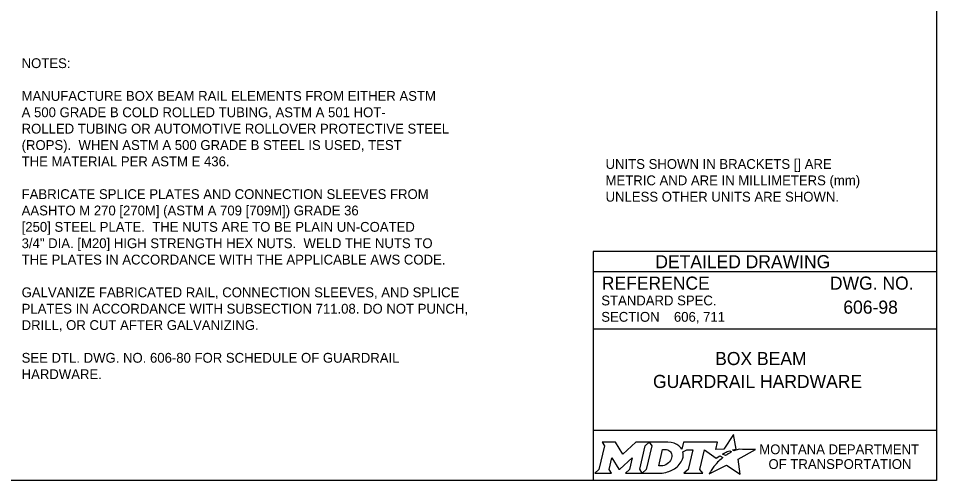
# Model space of a CAD drawing. Extents: x 49991.4 to 50021, y 49987.6 to 50011.4.
# Drawn here: x 50011.14 to 50016.75, y 49987.8 to 49990.62 of the extents above; entities that cross this region are included whole.
import ezdxf

# ---------------------------------------------------------------- set-up
doc = ezdxf.new("R2010")
doc.units = 0
for name, color, linetype in [('Default', 7, 'Continuous'), ('Level 1', 7, 'Continuous'), ('Level 2', 7, 'Continuous'), ('Level 5', 7, 'Continuous')]:
    doc.layers.add(name, color=color, linetype=linetype)

msp = doc.modelspace()

# ---------------------------------------------------------------- linework, layer by layer
at = {"layer": 'Default'}
for points in [[(50015.5126, 49987.9811), (50015.5023, 49987.9867), (50015.5139, 49987.9895), (50015.5255, 49987.9915), (50015.5081, 49988.0816), (50015.4486, 49987.9903), (50015.4013, 49987.9896), (50015.4116, 49988.0337), (50015.2024, 49988.0338), (50015.1923, 49987.9913), (50015.1865, 49987.9996)], [(50014.7056, 49988.0338), (50014.7197, 49988.0104), (50014.6862, 49987.8671), (50014.6605, 49987.8446), (50014.7621, 49987.8446), (50014.7486, 49987.8674), (50014.7648, 49987.9375), (50014.8085, 49987.8685), (50014.8138, 49987.8685), (50014.8889, 49987.938), (50014.8725, 49987.8669), (50014.8478, 49987.8449), (50014.9494, 49987.8449), (50014.9356, 49987.8682), (50014.9688, 49988.0106)], [(50014.9688, 49988.0106), (50014.9941, 49988.0338), (50014.9117, 49988.0338), (50014.8321, 49987.9608), (50014.7876, 49988.0335), (50014.7056, 49988.0338)], [(50015.1077, 49988.0338), (50014.9941, 49988.0338), (50015.0088, 49988.0109), (50014.9749, 49987.8671), (50014.9494, 49987.8449), (50015.06, 49987.8449)], [(50015.1317, 49987.9471), (50015.1305, 49987.939), (50015.1273, 49987.9297), (50015.1231, 49987.9215), (50015.1175, 49987.914), (50015.111, 49987.9071), (50015.1031, 49987.9008), (50015.0948, 49987.8961), (50015.0857, 49987.8922), (50015.0766, 49987.8899), (50015.0674, 49987.889), (50015.0515, 49987.889), (50015.0751, 49987.989), (50015.0911, 49987.989), (50015.0987, 49987.9884), (50015.1063, 49987.9865), (50015.1129, 49987.9835), (50015.119, 49987.9793), (50015.1238, 49987.9743), (50015.1275, 49987.9683), (50015.1302, 49987.9621), (50015.1318, 49987.9547), (50015.1318, 49987.9517), (50015.1317, 49987.9471)], [(50015.1991, 49987.9747), (50015.2237, 49987.9878), (50015.2606, 49987.9878), (50015.232, 49987.8673), (50015.2045, 49987.8446), (50015.3207, 49987.8446), (50015.3037, 49987.8675), (50015.3319, 49987.9877), (50015.4032, 49987.936), (50015.4243, 49987.9511), (50015.444, 49987.9402)], [(50015.3882, 49987.8843), (50015.3729, 49987.8599), (50015.3682, 49987.8524), (50015.3624, 49987.8438), (50015.3601, 49987.8395), (50015.4654, 49987.8926), (50015.5493, 49987.8375), (50015.5362, 49987.9302), (50015.6431, 49987.9886), (50015.5938, 49987.9894), (50015.5637, 49987.9898), (50015.5429, 49987.9901), (50015.5361, 49987.9886), (50015.5312, 49987.9874), (50015.5228, 49987.9851), (50015.5126, 49987.9811)], [(50015.4622, 49987.9535), (50015.4598, 49987.9518), (50015.4415, 49987.9614), (50015.4518, 49987.9671), (50015.4559, 49987.9693), (50015.4645, 49987.9733), (50015.4702, 49987.9759), (50015.4781, 49987.9789), (50015.4854, 49987.9816), (50015.4972, 49987.9742), (50015.4932, 49987.9721), (50015.4886, 49987.9696), (50015.4844, 49987.9674), (50015.4794, 49987.9645), (50015.4775, 49987.9634), (50015.4748, 49987.9618), (50015.4723, 49987.9604), (50015.47, 49987.9588), (50015.4674, 49987.957), (50015.4647, 49987.9552), (50015.4622, 49987.9535)], [(50015.4021, 49987.9004), (50015.4021, 49987.9004)], [(50015.1057, 49987.8522), (50015.1141, 49987.8548), (50015.1271, 49987.8602), (50015.1475, 49987.8712)]]:
    msp.add_lwpolyline(points, dxfattribs=at)
for centre, radius, start, end in [((50015.1308, 49987.9554), 0.0709, 339.5329, 15.8582), ((50015.0868, 49987.9727), 0.1183, 300.9103, 339.1383)]:
    msp.add_arc(centre, radius, start, end, dxfattribs=at)
for centre, major_axis, ratio, start_param, end_param in [((50015.1056, 49987.9864), (0.0834, -0.0037), 0.568097, 0.61298, 1.570796), ((50015.1612, 49987.9937), (0.0361, -0.0295), 0.469099, 1.225588, 1.570796), ((50015.3952, 49987.8923), (-0.00694, -0.00806), 0.008222, 0, 3.137361), ((50015.4119, 49987.9106), (-0.0098, -0.0102), 0.016458, 3.141593, 6.279097), ((50015.4329, 49987.9305), (-0.0112, -0.0097), 0.021651, 3.157348, 6.283185), ((50015.0603, 49987.9932), (0, 0.1484), 0.987302, 3.139398, 3.456847)]:
    msp.add_ellipse(centre, major_axis=major_axis, ratio=ratio, start_param=start_param, end_param=end_param, dxfattribs=at)
at = {"layer": 'Level 1'}
msp.add_lwpolyline([(49999.3835, 49998.9992), (50016.7501, 49998.9992), (50016.7501, 49987.7988), (49999.3835, 49987.7988)], close=True, dxfattribs=at)
at = {"layer": 'Level 5'}
for p, q in [((50016.7501, 49989.1988), (50014.6501, 49989.1988)), ((50014.6501, 49989.1988), (50014.6501, 49987.7988)), ((50016.7501, 49989.0738), (50014.6501, 49989.0738)), ((50016.3862, 49988.8587), (50016.3862, 49988.8587)), ((50015.1444, 49988.7993), (50015.1444, 49988.7993)), ((50016.7501, 49988.7238), (50014.6501, 49988.7238)), ((50015.7001, 49988.4747), (50015.7001, 49988.4747)), ((50016.7501, 49988.1057), (50014.6501, 49988.1057))]:
    msp.add_line(p, q, dxfattribs=at)

# ---------------------------------------------------------------- texts
at = {"layer": 'Default'}
for s, p in [('MONTANA DEPARTMENT', (50015.6663, 49987.96)), ('OF TRANSPORTATION', (50015.7225, 49987.87))]:
    msp.add_text(s, height=0.06, dxfattribs=at).set_placement(p)
at = {"layer": 'Level 2'}
for s, height, p in [('NOTES:', 0.06, (50011.1578, 49990.3191)), ('MANUFACTURE BOX BEAM RAIL ELEMENTS FROM EITHER ASTM', 0.06, (50011.1578, 49990.1191)), ('A 500 GRADE B COLD ROLLED TUBING, ASTM A 501 HOT-', 0.06, (50011.1578, 49990.0191)), ('ROLLED TUBING OR AUTOMOTIVE ROLLOVER PROTECTIVE STEEL', 0.06, (50011.1578, 49989.9191)), ('(ROPS).  WHEN ASTM A 500 GRADE B STEEL IS USED, TEST', 0.06, (50011.1578, 49989.8191)), ('THE MATERIAL PER ASTM E 436. ', 0.06, (50011.1578, 49989.7191)), ('UNITS SHOWN IN BRACKETS [] ARE ', 0.06, (50014.7268, 49989.7032)), ('METRIC AND ARE IN MILLIMETERS (mm) ', 0.06, (50014.7268, 49989.6032)), ('FABRICATE SPLICE PLATES AND CONNECTION SLEEVES FROM', 0.06, (50011.1578, 49989.5191)), ('UNLESS OTHER UNITS ARE SHOWN.', 0.06, (50014.7268, 49989.5032)), ('AASHTO M 270 [270M] (ASTM A 709 [709M]) GRADE 36 ', 0.06, (50011.1578, 49989.4191)), ('[250] STEEL PLATE.  THE NUTS ARE TO BE PLAIN UN-COATED ', 0.06, (50011.1578, 49989.3191)), ('3/4" DIA. [M20] HIGH STRENGTH HEX NUTS.  WELD THE NUTS TO', 0.06, (50011.1578, 49989.2191)), ('THE PLATES IN ACCORDANCE WITH THE APPLICABLE AWS CODE.', 0.06, (50011.1578, 49989.1191)), ('GALVANIZE FABRICATED RAIL, CONNECTION SLEEVES, AND SPLICE ', 0.06, (50011.1578, 49988.9191)), ('PLATES IN ACCORDANCE WITH SUBSECTION 711.08. DO NOT PUNCH,', 0.06, (50011.1578, 49988.8191)), ('606-98', 0.08, (50016.1798, 49988.8187)), ('606, 711', 0.06, (50015.1444, 49988.7693)), ('DRILL, OR CUT AFTER GALVANIZING.', 0.06, (50011.1578, 49988.7191)), ('SEE DTL. DWG. NO. 606-80 FOR SCHEDULE OF GUARDRAIL', 0.06, (50011.1578, 49988.5191)), ('BOX BEAM', 0.08, (50015.3965, 49988.5047)), ('HARDWARE.', 0.06, (50011.1578, 49988.4191)), ('GUARDRAIL HARDWARE', 0.08, (50015.0167, 49988.3647))]:
    msp.add_text(s, height=height, dxfattribs=at).set_placement(p)
at = {"layer": 'Level 5'}
for s, height, p in [('DETAILED DRAWING', 0.0799, (50015.0311, 49989.0963)), ('REFERENCE', 0.08, (50014.7037, 49988.9654)), ('DWG. NO.', 0.08, (50016.0979, 49988.9654)), ('STANDARD SPEC.', 0.06, (50014.7004, 49988.8694)), ('SECTION', 0.06, (50014.7004, 49988.7694))]:
    msp.add_text(s, height=height, dxfattribs=at).set_placement(p)

doc.saveas('drawing.dxf')
